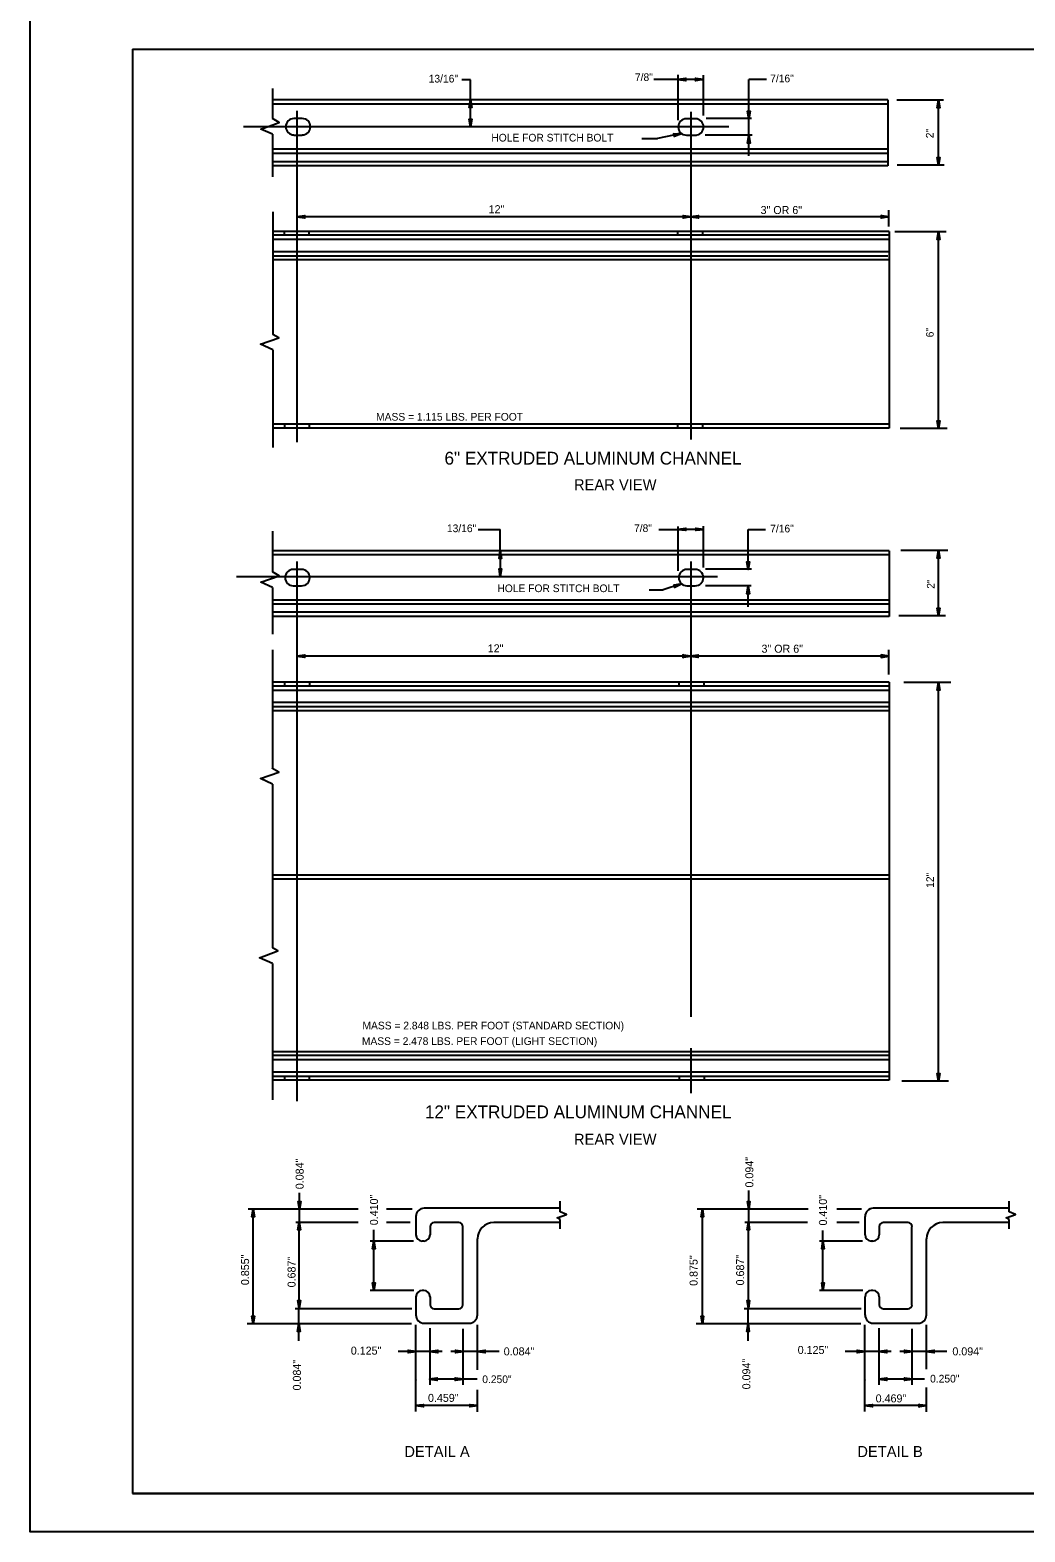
# Model space of a CAD drawing. Extents: x 647822 to 649292, y 298458 to 299646.
# Drawn here: x 647822 to 648211, y 298458 to 299044 of the extents above; entities that cross this region are included whole.
import ezdxf

# ---------------------------------------------------------------- set-up
doc = ezdxf.new("R2010")
doc.units = 0
for name, color, linetype in [('1', 7, 'Continuous'), ('2', 7, 'Continuous'), ('3', 7, 'Continuous'), ('XCS-GRID-MIN', 7, 'Continuous')]:
    doc.layers.add(name, color=color, linetype=linetype)

# ---------------------------------------------------------------- blocks, each defined once
blk = doc.blocks.new('RARROW')
at = {"layer": '3'}
blk.add_lwpolyline([(-2.2695, 0.285), (-2.184875, 0.12075), (0, 0), (-2.2695, 0.285), (-2.38575, 0.384625), (0, 0), (-2.183125, -0.108), (-2.262875, -0.2705), (0, 0), (-2.38575, -0.379125), (-2.262875, -0.2705)], dxfattribs=at)

msp = doc.modelspace()

# ---------------------------------------------------------------- linework, layer by layer
at = {"layer": '1'}
for p, q in [((647862.31, 299036.63), (648648.31, 299036.63)), ((647862.31, 299036.63), (647862.31, 298472.63)), ((648648.31, 298472.63), (647862.31, 298472.63)), ((647862.31, 298472.63), (648448.31, 298472.63))]:
    msp.add_line(p, q, dxfattribs=at)
at = {"layer": '2'}
for p, q in [((647917.06, 299021.35), (647917.06, 299009.6)), ((647994.44, 299024.72), (647991.03, 299024.72)), ((647994.44, 299016.47), (647994.44, 299024.72)), ((648075.69, 299024.85), (648066.06, 299024.85)), ((648075.44, 299024.85), (648068.52, 299024.85)), ((648075.56, 299008.97), (648075.56, 299026.6)), ((648085.31, 299024.85), (648075.56, 299024.85)), ((648085.44, 299024.85), (648085.06, 299024.85)), ((648085.44, 299024.85), (648085.31, 299024.85)), ((648085.44, 299010.72), (648085.44, 299026.48)), ((648103.19, 299009.47), (648103.19, 299024.85)), ((648110.12, 299024.85), (648103.19, 299024.85)), ((648157.44, 299016.85), (647917.06, 299016.85)), ((647994.44, 299006.35), (647994.44, 299016.85)), ((647994.44, 299015.22), (647994.44, 299016.6)), ((648157.44, 299016.85), (648157.44, 298991.1)), ((648179.19, 299016.72), (648160.94, 299016.72)), ((648177.31, 298991.35), (648177.31, 299016.72)), ((648157.44, 299015.22), (647917.06, 299015.22)), ((647928.69, 299009.6), (647925.44, 299009.6)), ((647928.69, 299009.6), (647925.44, 299009.6)), ((647926.69, 298883.22), (647926.69, 299012.6)), ((648082.31, 299009.47), (648078.69, 299009.47)), ((648080.56, 299012.22), (648080.56, 298884.22)), ((648104.19, 299009.6), (648086.56, 299009.6)), ((648103.19, 299002.97), (648103.19, 299009.47)), ((647905.69, 299006.47), (648095.31, 299006.47)), ((647922.19, 299006.35), (647922.19, 299006.35)), ((647922.19, 299006.35), (647922.19, 299006.35)), ((647927.06, 299006.35), (647927.06, 299006.35)), ((647927.06, 299006.35), (647927.06, 299006.35)), ((647931.94, 299006.35), (647931.94, 299006.35)), ((647931.94, 299006.35), (647931.94, 299006.35)), ((648076.81, 299003.72), (648067.44, 299001.72)), ((648075.81, 299006.35), (648075.81, 299006.35)), ((648075.81, 299006.35), (648075.81, 299006.35)), ((648076.19, 299006.35), (648076.19, 299006.35)), ((648076.19, 299006.35), (648076.19, 299006.35)), ((648080.69, 299006.35), (648080.69, 299006.35)), ((648080.69, 299006.35), (648080.69, 299006.35)), ((648081.06, 299006.35), (648081.06, 299006.35)), ((648081.06, 299006.35), (648081.06, 299006.35)), ((648085.44, 299006.35), (648085.44, 299006.35)), ((648085.44, 299006.35), (648085.44, 299006.35)), ((648085.94, 299006.35), (648085.94, 299006.35)), ((648085.94, 299006.35), (648085.94, 299006.35)), ((647917.06, 299003.47), (647917.06, 298986.85)), ((647925.44, 299003.1), (647928.69, 299003.1)), ((647925.44, 299003.1), (647928.69, 299003.1)), ((648061.31, 299001.72), (648067.44, 299001.72)), ((648078.81, 299003.1), (648082.69, 299003.1)), ((648104.44, 299003.1), (648086.06, 299003.1)), ((648103.19, 298994.97), (648103.19, 299002.97)), ((648157.44, 298997.6), (647917.06, 298997.6)), ((648157.44, 298995.97), (647917.06, 298995.97)), ((648157.44, 298992.72), (647917.06, 298992.72)), ((648157.44, 298991.1), (647917.06, 298991.1)), ((648179.56, 298991.35), (648161.19, 298991.35)), ((647917.19, 298973.1), (647917.19, 298925.22)), ((648080.56, 298971.22), (647926.69, 298971.22)), ((648157.94, 298971.22), (648080.56, 298971.22)), ((648157.94, 298967.35), (648157.94, 298973.85)), ((648158.06, 298965.47), (647917.19, 298965.47)), ((648158.06, 298963.97), (647917.19, 298963.97)), ((647921.69, 298963.97), (647921.69, 298965.47)), ((647931.44, 298963.97), (647931.44, 298965.47)), ((648075.44, 298963.85), (648075.44, 298965.47)), ((648085.19, 298963.97), (648085.19, 298965.47)), ((648158.06, 298965.47), (648158.06, 298888.6)), ((648180.31, 298965.35), (648160.19, 298965.35)), ((648177.31, 298888.47), (648177.31, 298965.35)), ((648158.06, 298962.35), (647917.19, 298962.35)), ((648158.06, 298957.47), (647917.19, 298957.47)), ((648157.44, 298955.85), (647917.19, 298955.85)), ((648158.06, 298954.35), (647917.19, 298954.35)), ((647917.19, 298919.22), (647917.19, 298881.1)), ((648158.06, 298890.22), (647917.19, 298890.22)), ((648158.06, 298888.72), (647917.19, 298888.72)), ((647921.81, 298888.72), (647921.81, 298890.22)), ((647931.56, 298888.72), (647931.56, 298890.22)), ((648075.44, 298888.6), (648075.44, 298890.22)), ((648085.19, 298888.6), (648085.19, 298890.22)), ((648180.69, 298888.47), (648162.31, 298888.47)), ((647917.06, 298848.5), (647917.06, 298832.5)), ((647997.48, 298849.15), (648006.06, 298849.15)), ((648006.06, 298840.75), (648006.06, 298849.15)), ((648068, 298849.15), (648075.56, 298849.15)), ((648075.56, 298833), (648075.56, 298850.27)), ((648085.44, 298849.15), (648075.56, 298849.15)), ((648085.44, 298834.25), (648085.44, 298850.4)), ((648102.94, 298833.5), (648102.94, 298849.15)), ((648102.94, 298849.15), (648109.67, 298849.15)), ((648158.06, 298840.75), (647917.06, 298840.75)), ((648006.06, 298840.75), (648006.06, 298841)), ((648006.06, 298840.75), (648006.06, 298830.75)), ((648158.06, 298840.75), (648158.06, 298815.13)), ((648180.94, 298840.88), (648162.56, 298840.88)), ((648177.31, 298815.38), (648177.31, 298840.88)), ((648158.06, 298839.13), (647917.06, 298839.13)), ((647928.44, 298833.5), (647925.19, 298833.5)), ((647928.44, 298833.5), (647925.19, 298833.5)), ((647926.69, 298625.88), (647926.69, 298836.63)), ((648082.19, 298833.5), (648078.94, 298833.5)), ((648082.19, 298833.5), (648078.94, 298833.5)), ((648080.56, 298836.63), (648080.56, 298658.79)), ((648104.19, 298833.63), (648086.19, 298833.63)), ((647902.94, 298830.75), (648090.94, 298830.75)), ((647921.94, 298830.38), (647921.94, 298830.38)), ((647921.94, 298830.38), (647921.94, 298830.38)), ((647926.81, 298830.38), (647926.81, 298830.38)), ((647926.81, 298830.38), (647926.81, 298830.38)), ((647931.56, 298830.38), (647931.56, 298830.38)), ((647931.56, 298830.38), (647931.56, 298830.38)), ((648076.81, 298827.88), (648069.69, 298825.5)), ((648075.81, 298830.38), (648075.81, 298830.38)), ((648075.81, 298830.38), (648075.81, 298830.38)), ((648080.56, 298830.38), (648080.56, 298830.38)), ((648080.56, 298830.38), (648080.56, 298830.38)), ((648085.44, 298830.38), (648085.44, 298830.38)), ((648085.44, 298830.38), (648085.44, 298830.38)), ((647917.06, 298826.5), (647917.06, 298808.25)), ((647925.19, 298827.13), (647928.44, 298827.13)), ((647925.19, 298827.13), (647928.44, 298827.13)), ((648064.19, 298825.5), (648069.69, 298825.5)), ((648078.94, 298827.13), (648082.19, 298827.13)), ((648078.94, 298827.13), (648082.19, 298827.13)), ((648104.06, 298827.13), (648086.19, 298827.13)), ((648102.94, 298818.88), (648102.94, 298827)), ((648158.06, 298821.5), (647917.06, 298821.5)), ((648158.06, 298819.88), (647917.06, 298819.88)), ((648158.06, 298816.75), (647917.06, 298816.75)), ((648158.06, 298815.13), (647917.06, 298815.13)), ((648180.06, 298815.38), (648161.81, 298815.38)), ((647917.06, 298802.13), (647917.06, 298755.75)), ((648080.44, 298799.63), (647926.69, 298799.63)), ((648157.94, 298799.63), (648080.44, 298799.63)), ((648157.94, 298792.5), (648157.94, 298802.13)), ((648158.06, 298789.5), (647917.06, 298789.5)), ((648158.06, 298787.88), (647917.06, 298787.88)), ((647921.94, 298787.88), (647921.94, 298789.5)), ((647931.69, 298787.88), (647931.69, 298789.5)), ((648075.94, 298787.88), (648075.94, 298789.5)), ((648085.69, 298787.88), (648085.69, 298789.5)), ((648158.06, 298789.5), (648158.06, 298634)), ((648182.06, 298789.38), (648163.69, 298789.38)), ((648177.31, 298633.63), (648177.31, 298789.38)), ((648158.06, 298786.25), (647917.06, 298786.25)), ((648158.06, 298781.5), (647917.06, 298781.5)), ((648158.06, 298779.88), (647917.06, 298779.88)), ((648158.06, 298778.25), (647917.06, 298778.25)), ((647917.06, 298749.63), (647917.06, 298685.75)), ((648158.06, 298714.13), (647917.06, 298714.13)), ((648158.06, 298712.5), (647917.06, 298712.5)), ((647917.06, 298679.63), (647917.06, 298626.38)), ((648080.56, 298646.52), (648080.56, 298628.93)), ((648158.06, 298645.13), (647917.06, 298645.13)), ((648158.06, 298643.63), (647917.06, 298643.63)), ((648158.06, 298642), (647917.06, 298642)), ((648158.06, 298637.13), (647917.06, 298637.13)), ((648158.06, 298635.5), (647917.06, 298635.5)), ((647921.94, 298634), (647921.94, 298635.5)), ((647931.56, 298634), (647931.56, 298635.5)), ((648076.06, 298634), (648076.06, 298635.63)), ((648085.81, 298634), (648085.81, 298635.5)), ((648158.06, 298634), (647917.06, 298634)), ((648181.19, 298633.63), (648162.94, 298633.63)), ((647927.63, 298578.45), (647927.63, 298590.07)), ((648103.11, 298578.45), (648103.11, 298590.92)), ((647950.53, 298583.7), (647907.54, 298583.7)), ((647909.54, 298538.95), (647909.54, 298583.7)), ((647971.66, 298583.7), (647961.55, 298583.7)), ((648029.41, 298584.07), (647976.29, 298584.07)), ((648029.41, 298582.7), (648029.41, 298586.82)), ((648126.36, 298583.7), (648083.02, 298583.7)), ((648085.02, 298538.95), (648085.02, 298583.7)), ((648147.15, 298583.7), (648137.6, 298583.7)), ((648204.9, 298584.07), (648151.77, 298584.07)), ((648204.9, 298582.7), (648204.9, 298586.82)), ((647950.53, 298578.45), (647926.13, 298578.45)), ((647927.5, 298544.95), (647927.5, 298578.57)), ((647956.66, 298551.95), (647956.66, 298575.58)), ((647970.79, 298578.45), (647961.55, 298578.45)), ((647973.04, 298580.82), (647973.04, 298573.7)), ((647978.66, 298576.82), (647978.66, 298573.7)), ((647989.91, 298578.45), (647980.16, 298578.45)), ((647991.41, 298546.32), (647991.41, 298576.82)), ((648029.41, 298578.45), (648003.54, 298578.45)), ((648029.41, 298575.95), (648029.41, 298579.7)), ((648126.14, 298578.45), (648101.61, 298578.45)), ((648102.99, 298544.95), (648102.99, 298578.57)), ((648146.27, 298578.45), (648137.6, 298578.45)), ((648148.52, 298580.82), (648148.52, 298573.7)), ((648154.15, 298576.82), (648154.15, 298573.7)), ((648165.4, 298578.45), (648155.65, 298578.45)), ((648166.9, 298546.32), (648166.9, 298576.82)), ((648204.9, 298578.45), (648179.02, 298578.45)), ((648204.9, 298575.95), (648204.9, 298579.7)), ((647972.16, 298571.2), (647955.28, 298571.2)), ((647976.16, 298571.2), (647975.54, 298571.2)), ((647997.16, 298542.32), (647997.16, 298572.07)), ((648147.65, 298571.2), (648130.77, 298571.2)), ((648132.14, 298551.95), (648132.14, 298575.4)), ((648151.65, 298571.2), (648151.02, 298571.2)), ((648172.65, 298542.32), (648172.65, 298572.07)), ((647972.29, 298551.95), (647955.28, 298551.95)), ((647973.04, 298549.45), (647973.04, 298542.32)), ((647976.16, 298551.95), (647975.54, 298551.95)), ((647978.66, 298549.45), (647978.66, 298546.32)), ((648147.77, 298551.95), (648130.77, 298551.95)), ((648148.52, 298549.45), (648148.52, 298542.32)), ((648151.65, 298551.95), (648151.02, 298551.95)), ((648154.15, 298549.45), (648154.15, 298546.32)), ((647971.54, 298544.82), (647925.88, 298544.82)), ((647927.38, 298532.31), (647927.38, 298544.82)), ((647980.16, 298544.82), (647989.91, 298544.82)), ((648147.02, 298544.82), (648101.36, 298544.82)), ((648102.86, 298532.23), (648102.86, 298544.82)), ((648155.65, 298544.82), (648165.4, 298544.82)), ((647971.41, 298538.95), (647907.16, 298538.95)), ((647973.04, 298504.7), (647973.04, 298538.45)), ((647976.29, 298539.2), (647993.91, 298539.2)), ((647978.66, 298515.07), (647978.66, 298537.2)), ((647991.54, 298515.07), (647991.54, 298536.95)), ((647997.16, 298520.96), (647997.16, 298538.57)), ((648146.9, 298538.95), (648082.65, 298538.95)), ((648148.52, 298504.7), (648148.52, 298538.45)), ((648151.77, 298539.2), (648169.4, 298539.2)), ((648154.15, 298515.07), (648154.15, 298537.2)), ((648167.02, 298515.07), (648167.02, 298536.95)), ((648172.65, 298521.21), (648172.65, 298538.57)), ((647973.04, 298528.08), (647966.15, 298528.08)), ((647978.66, 298528.08), (647973.04, 298528.08)), ((647983.36, 298528.08), (647978.66, 298528.08)), ((647991.54, 298528.08), (647986.73, 298528.08)), ((647997.16, 298528.08), (647991.54, 298528.08)), ((648005.64, 298528.08), (647997.16, 298528.08)), ((648154.15, 298528.08), (648140.75, 298528.08)), ((648158.74, 298528.08), (648154.15, 298528.08)), ((648172.65, 298528.08), (648162.11, 298528.08)), ((648180.55, 298528.08), (648172.65, 298528.08)), ((647973.04, 298517.07), (647973.04, 298516.95)), ((647997.03, 298517.32), (647978.41, 298517.32)), ((648148.52, 298517.07), (648148.52, 298516.95)), ((648171.78, 298517.32), (648154.15, 298517.32)), ((647997.16, 298504.57), (647997.16, 298513.19)), ((648172.65, 298504.57), (648172.65, 298514.02)), ((647997.16, 298506.95), (647973.04, 298506.95)), ((648172.65, 298506.95), (648148.52, 298506.95))]:
    msp.add_line(p, q, dxfattribs=at)
for points in [[(647917.06, 299003.47), (647912.44, 299005.47), (647919.69, 299007.97), (647917.06, 299009.6)], [(647917.19, 298919.22), (647912.31, 298921.47), (647919.56, 298923.97), (647917.19, 298925.22)], [(647917.06, 298826.38), (647912.44, 298828.5), (647919.69, 298831), (647917.06, 298832.5)], [(647917.06, 298749.63), (647912.31, 298751.88), (647919.56, 298754.38), (647916.81, 298755.88)], [(647917.06, 298679.63), (647911.94, 298681.88), (647919.19, 298684.5), (647917.06, 298685.75)], [(648029.41, 298579.7), (648028.29, 298580.32), (648031.91, 298581.57), (648029.41, 298582.7)], [(648204.9, 298579.7), (648203.77, 298580.32), (648207.4, 298581.57), (648204.9, 298582.7)]]:
    msp.add_lwpolyline(points, dxfattribs=at)
for centre, radius, start, end in [((647925.43, 299006.37), 3.2, 90, 180), ((647925.43, 299006.37), 3.2, 90, 180), ((647928.68, 299006.37), 3.2, 0, 90), ((647928.68, 299006.37), 3.2, 0, 90), ((648078.77, 299006.29), 3.2, 90, 180), ((648082.29, 299006.29), 3.2, 0, 90), ((648082.29, 299006.29), 3.2, 0, 90), ((647925.43, 299006.36), 3.2, 180, 270), ((647925.43, 299006.36), 3.2, 180, 270), ((647928.68, 299006.36), 3.2, 270, 0), ((647928.68, 299006.36), 3.2, 270, 0), ((648078.77, 299006.28), 3.2, 180, 270), ((648082.29, 299006.28), 3.2, 270, 0), ((648082.29, 299006.28), 3.2, 270, 0), ((647925.18, 298830.32), 3.2, 90, 180), ((647925.18, 298830.32), 3.2, 90, 180), ((647928.42, 298830.32), 3.2, 0, 90), ((647928.42, 298830.32), 3.2, 0, 90), ((648078.98, 298830.32), 3.2, 90, 180), ((648078.98, 298830.32), 3.2, 90, 180), ((648082.22, 298830.32), 3.2, 0, 90), ((648082.22, 298830.32), 3.2, 0, 90), ((647925.18, 298830.31), 3.2, 180, 270), ((647925.18, 298830.31), 3.2, 180, 270), ((647928.42, 298830.31), 3.2, 270, 0), ((647928.42, 298830.31), 3.2, 270, 0), ((648078.98, 298830.31), 3.2, 180, 270), ((648078.98, 298830.31), 3.2, 180, 270), ((648082.22, 298830.31), 3.2, 270, 0), ((648082.22, 298830.31), 3.2, 270, 0), ((647976.3, 298580.83), 3.2, 90.36728, 180), ((648151.78, 298580.83), 3.2, 90.36728, 180), ((647980.24, 298576.84), 1.6, 90, 180), ((647989.86, 298576.84), 1.6, 0, 90), ((648003.51, 298572.04), 6.4, 90, 180), ((648155.72, 298576.84), 1.6, 90, 180), ((648165.35, 298576.84), 1.6, 0, 90), ((648178.99, 298572.04), 6.4, 90, 180), ((647975.56, 298573.67), 2.46, 180, 270), ((647976.17, 298573.67), 2.46, 270, 0), ((648151.04, 298573.67), 2.46, 180, 270), ((648151.66, 298573.67), 2.46, 270, 0), ((647975.56, 298549.46), 2.46, 90, 180), ((647976.17, 298549.46), 2.46, 0, 90), ((647980.24, 298546.36), 1.6, 180, 270), ((647989.86, 298546.36), 1.6, 270, 0), ((648151.04, 298549.46), 2.46, 90, 180), ((648151.66, 298549.46), 2.46, 0, 90), ((648155.72, 298546.36), 1.6, 180, 270), ((648165.35, 298546.36), 1.6, 270, 0), ((647976.3, 298542.35), 3.2, 180, 270), ((647993.9, 298542.35), 3.2, 270, 0), ((648151.78, 298542.35), 3.2, 180, 270), ((648169.39, 298542.35), 3.2, 270, 0)]:
    msp.add_arc(centre, radius, start, end, dxfattribs=at)
at = {"layer": 'XCS-GRID-MIN'}
msp.add_lwpolyline([(647822.31, 299051.63), (648663.31, 299051.63), (648663.31, 298457.63), (647822.31, 298457.63)], close=True, dxfattribs=at)

# ---------------------------------------------------------------- block references
at = {"layer": '2', "xscale": 1.2574347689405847}
for p, yscale, rotation in [((648075.56, 299024.85), 1.3092961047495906, 180), ((647994.44, 299016.85), 1.3092961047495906, 89.99999999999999), ((648177.31, 299016.72), 1.3092961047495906, 89.99999999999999), ((648103.19, 299009.47), 1.3092961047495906, -90.00000000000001), ((647994.44, 299006.35), 1.3092961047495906, -90.00000000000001), ((648076.81, 299003.72), 1.3092961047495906, 12.912406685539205), ((648103.19, 299002.97), 1.3092961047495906, 89.99999999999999), ((648177.31, 298991.35), 1.3092961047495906, -90.00000000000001), ((647926.69, 298971.22), 1.3092961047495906, 180), ((648080.56, 298971.22), 1.3092961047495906, 180), ((648177.31, 298965.35), 1.3092961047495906, 89.99999999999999), ((648177.31, 298888.47), 1.3092961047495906, -90.00000000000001), ((648075.56, 298849.15), 1.3092961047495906, 180), ((648006.06, 298840.75), 1.3092961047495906, 89.99999999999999), ((648177.31, 298840.88), 1.3092961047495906, 89.99999999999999), ((648006.06, 298830.75), 1.3092961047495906, -90.00000000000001), ((648102.94, 298833.5), 1.3092961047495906, -90.00000000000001), ((648076.81, 298827.88), 1.3092961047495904, 19.076864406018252), ((648102.94, 298827), 1.3092961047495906, 89.99999999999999), ((648177.31, 298815.38), 1.3092961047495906, -90.00000000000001), ((647926.69, 298799.63), 1.3092961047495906, 180), ((648080.44, 298799.63), 1.3092961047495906, 180), ((648177.31, 298789.38), 1.3092961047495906, 89.99999999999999), ((648177.31, 298633.63), 1.3092961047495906, -90.00000000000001), ((647909.54, 298583.7), 1.3092961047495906, 89.99999999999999), ((647927.63, 298583.7), 1.3092961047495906, -90.00000000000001), ((648085.02, 298583.7), 1.3092961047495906, 89.99999999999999), ((648103.11, 298583.7), 1.3092961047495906, -90.00000000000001), ((647927.5, 298578.57), 1.3092961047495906, 89.99999999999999), ((648102.99, 298578.57), 1.3092961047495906, 89.99999999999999), ((647956.66, 298571.2), 1.3092961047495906, 89.99999999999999), ((648132.14, 298571.2), 1.3092961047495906, 89.99999999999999), ((647956.66, 298551.95), 1.3092961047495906, -90.00000000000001), ((648132.14, 298551.95), 1.3092961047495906, -90.00000000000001), ((647927.5, 298544.95), 1.3092961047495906, -90.00000000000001), ((648102.99, 298544.95), 1.3092961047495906, -90.00000000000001), ((647909.54, 298538.95), 1.3092961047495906, -90.00000000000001), ((648085.02, 298538.95), 1.3092961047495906, -90.00000000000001), ((647927.38, 298538.95), 1.3092961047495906, 89.99999999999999), ((648102.86, 298538.95), 1.3092961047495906, 89.99999999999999), ((647978.66, 298528.08), 1.3092961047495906, 180), ((647997.16, 298528.08), 1.3092961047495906, 180), ((648154.15, 298528.08), 1.3092961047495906, 180), ((648172.65, 298528.08), 1.3092961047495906, 180), ((647978.41, 298517.32), 1.3092961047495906, 180), ((648154.15, 298517.32), 1.3092961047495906, 180), ((647973.04, 298506.95), 1.3092961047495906, 180), ((648148.52, 298506.95), 1.3092961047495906, 180)]:
    msp.add_blockref('RARROW', p, dxfattribs=dict(at, yscale=yscale, rotation=rotation))
for p, yscale in [((648085.31, 299024.85), 1.3092961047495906), ((648080.56, 298971.22), 1.3092961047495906), ((648157.94, 298971.22), 1.3092961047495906), ((648085.44, 298849.15), 1.3092961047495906), ((648080.44, 298799.63), 1.3092961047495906), ((648157.94, 298799.63), -1.3092961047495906), ((647973.04, 298528.08), 1.3092961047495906), ((647991.54, 298528.08), 1.3092961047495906), ((648148.52, 298528.08), 1.3092961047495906), ((648167.02, 298528.08), 1.3092961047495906), ((647991.41, 298517.32), 1.3092961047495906), ((648167.02, 298517.32), 1.3092961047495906), ((647997.16, 298506.95), 1.3092961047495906), ((648172.65, 298506.95), 1.3092961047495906)]:
    msp.add_blockref('RARROW', p, dxfattribs=dict(at, yscale=yscale))

# ---------------------------------------------------------------- texts
at = {"layer": '2'}
for s, height, p in [('7/8"', 3, (648058.67, 299024.22)), ('13/16"', 3, (647978.09, 299023.64)), ('7/16"', 3, (648111.51, 299023.71)), ('HOLE FOR STITCH BOLT', 3, (648002.56, 299000.6)), ('12"', 3.125, (648001.51, 298972.6)), ('3" OR 6"', 3.125, (648107.77, 298972.28)), ('MASS = 1.115 LBS. PER FOOT', 3, (647957.54, 298891.6)), ('6" EXTRUDED ALUMINUM CHANNEL', 5, (647984.26, 298874.44)), ('REAR VIEW', 4.3, (648034.85, 298864.44)), ('13/16"', 3, (647985.21, 298848.05)), ('7/8"', 3, (648058.32, 298848.1)), ('7/16"', 3, (648111.51, 298847.95)), ('HOLE FOR STITCH BOLT', 3, (648004.94, 298824.63)), ('12"', 3.125, (648001.15, 298801.11)), ('3" OR 6"', 3.125, (648108.13, 298800.97)), ('MASS = 2.848 LBS. PER FOOT (STANDARD SECTION)', 3, (647952.21, 298653.87)), ('MASS = 2.478 LBS. PER FOOT (LIGHT SECTION)', 3, (647951.98, 298647.8)), ('12" EXTRUDED ALUMINUM CHANNEL', 5, (647976.61, 298619.18)), ('REAR VIEW', 4.3, (648034.85, 298608.83)), ('0.125"', 3.125, (647947.65, 298526.88)), ('0.084"', 3.125, (648007.4, 298526.58)), ('0.125"', 3.125, (648122.27, 298527.13)), ('0.094"', 3.125, (648182.71, 298526.59)), ('0.250"', 3, (647999.02, 298515.75)), ('0.250"', 3, (648174, 298515.99)), ('0.459"', 3.125, (647977.81, 298508.43)), ('0.469"', 3.125, (648152.73, 298508.22)), ('DETAIL A', 4.3, (647968.56, 298486.88)), ('DETAIL B', 4.3, (648145.56, 298486.88))]:
    msp.add_text(s, height=height, dxfattribs=at).set_placement(p)
for s, height, p in [('2"', 3, (648175.37, 299001.87)), ('6"', 3, (648175.4, 298924.13)), ('2"', 3, (648175.76, 298825.95)), ('12"', 3, (648175.5, 298709.16)), ('0.084"', 3.125, (647929.22, 298591.46)), ('0.094"', 3.125, (648104.94, 298592.12)), ('0.410"', 3.125, (647958.26, 298577.4)), ('0.410"', 3.125, (648133.69, 298577.29)), ('0.855"', 3.125, (647907.9, 298554.01)), ('0.687"', 3.125, (647926.07, 298553.14)), ('0.875"', 3.125, (648083.15, 298553.72)), ('0.687"', 3.125, (648101.34, 298553.9)), ('0.084"', 3.125, (647928.14, 298512.89)), ('0.094"', 3.125, (648103.77, 298513.32))]:
    msp.add_text(s, height=height, rotation=90, dxfattribs=at).set_placement(p)

doc.saveas('drawing.dxf')
